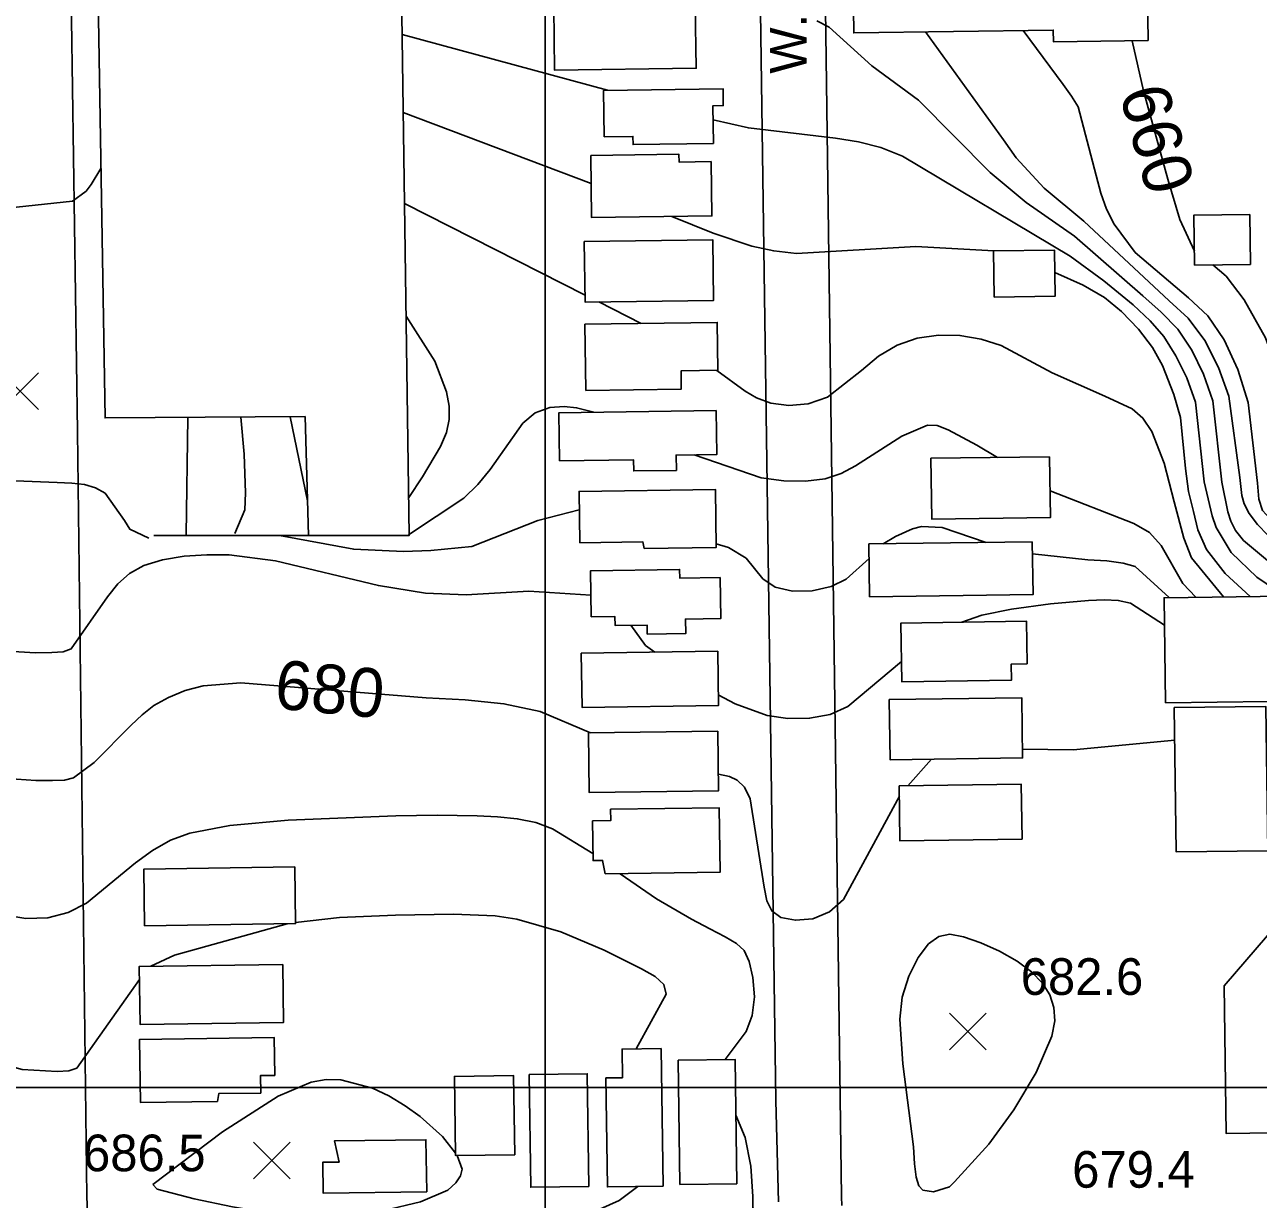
# Model space of a CAD drawing. Extents: x 79600 to 91800, y 75600 to 84400.
# Drawn here: x 80787 to 81292, y 77954 to 78435 of the extents above; entities that cross this region are included whole.
import ezdxf

# ---------------------------------------------------------------- set-up
doc = ezdxf.new("R2010")
doc.units = 0
for name, color, linetype in [('080-085$0$BLDG', 7, 'Continuous'), ('080-085$0$GRID', 7, 'Continuous'), ('080-085$0$INDEX', 7, 'Continuous'), ('080-085$0$INDXLBL', 7, 'Continuous'), ('080-085$0$INTER', 7, 'Continuous'), ('080-085$0$ROAD', 7, 'Continuous'), ('080-085$0$ROAD-NAME', 7, 'Continuous'), ('080-085$0$SPOTMARK', 7, 'Continuous'), ('080-085$0$SPOTS', 7, 'Continuous'), ('080-085$0$WALL', 7, 'Continuous')]:
    doc.layers.add(name, color=color, linetype=linetype)

# ---------------------------------------------------------------- blocks, each defined once
blk = doc.blocks.new('080-085$0$SPOTS')
at = {"layer": '080-085$0$SPOTMARK'}
for p, q in [((-0.5, -0.5), (0.5, 0.5)), ((-0.5, 0.5), (0.5, -0.5))]:
    blk.add_line(p, q, dxfattribs=at)

msp = doc.modelspace()

# ---------------------------------------------------------------- linework, layer by layer
at = {"layer": '080-085$0$BLDG'}
for points in [[(80925.81, 78506.36), (80926.78, 78456.84), (80816.71, 78454.12), (80819.72, 78274.15), (80901.62, 78274.69), (80903, 78226), (80944.3, 78226.06), (80940.99, 78458.77), (81076.3, 78462.25), (81074.62, 78582.1), (80949.62, 78579.81), (80950.92, 78507.27)], [(81125.3, 78509.93), (81126.36, 78431.78), (81208.04, 78432.89), (81208.1, 78428.14), (81246.86, 78428.67), (81246.24, 78474.46), (81223.47, 78474.15), (81222.97, 78511.25)], [(81003.49, 78442.16), (81061.46, 78442.98), (81061.82, 78417.26), (81003.85, 78416.45)], [(81024.15, 78389.23), (81035.94, 78389.4), (81035.99, 78386.06), (81068.88, 78386.52), (81068.66, 78401.93), (81072.91, 78401.99), (81072.81, 78408.93), (81023.89, 78408.25)], [(81018.64, 78381.59), (81054.77, 78382.09), (81054.82, 78378.88), (81067.93, 78379.07), (81068.24, 78356.85), (81019, 78356.16)], [(81288.5, 78357.46), (81288.78, 78337.02), (81265.95, 78336.71), (81265.67, 78357.15)], [(81016.01, 78346.36), (81068.6, 78347.09), (81068.95, 78322.27), (81016.35, 78321.54)], [(81183.63, 78342.52), (81208.53, 78342.85), (81208.79, 78323.95), (81183.89, 78323.61)], [(81016.66, 78285.43), (81055.73, 78285.97), (81055.63, 78293.42), (81070.7, 78293.63), (81070.43, 78313.23), (81016.28, 78312.47)], [(81005.85, 78256.55), (81036.19, 78256.98), (81036.26, 78252.44), (81053.7, 78252.69), (81053.61, 78258.94), (81070.22, 78259.17), (81069.96, 78277.14), (81005.57, 78276.24)], [(81206.56, 78258.28), (81206.9, 78233.37), (81158.27, 78232.72), (81157.93, 78257.62)], [(81014.15, 78223.07), (81039.94, 78223.44), (81040.53, 78220.7), (81070.05, 78221.11), (81069.72, 78244.86), (81013.86, 78244.08)], [(81199.46, 78223.46), (81199.76, 78201.83), (81132.84, 78200.93), (81132.55, 78222.55)], [(81018.86, 78192.67), (81028.56, 78192.81), (81028.61, 78189.19), (81041.7, 78189.37), (81041.75, 78185.66), (81057.53, 78185.88), (81057.44, 78191.79), (81071.88, 78191.99), (81071.64, 78208.81), (81055.09, 78208.58), (81055.04, 78212.12), (81018.59, 78211.61)], [(81197.4, 78173.47), (81190.84, 78173.38), (81190.93, 78166.75), (81145.98, 78166.14), (81145.66, 78190.19), (81197.16, 78190.89)], [(81014.75, 78177.86), (81070.62, 78178.64), (81070.93, 78156.41), (81015.06, 78155.63)], [(81140.89, 78158.89), (81141.23, 78134.19), (81195.5, 78134.93), (81195.17, 78159.62)], [(81257.61, 78155.57), (81258.41, 78096.48), (81295.89, 78096.99), (81295.09, 78156.07)], [(81017.66, 78145.17), (81070.68, 78145.91), (81071.02, 78121.51), (81018, 78120.77)], [(81195.28, 78101.64), (81194.97, 78124.17), (81144.97, 78123.49), (81145.27, 78100.96)], [(81024.59, 78087.48), (81023.46, 78092.99), (81019.6, 78092.93), (81019.37, 78109.18), (81026.85, 78109.28), (81026.79, 78113.94), (81071.21, 78114.56), (81071.58, 78088.14)], [(80897.42, 78090.31), (80897.75, 78067.15), (80835.94, 78066.28), (80835.62, 78089.44)], [(80892.52, 78050.42), (80892.85, 78026.71), (80834.05, 78025.88), (80833.71, 78049.6)], [(80889.24, 78005.02), (80883.38, 78004.93), (80883.48, 77997.76), (80866.3, 77997.52), (80865.73, 77994.38), (80834.24, 77993.94), (80833.88, 78019.74), (80889.03, 78020.51)], [(81048.23, 77959.64), (81047.44, 78015.99), (81031.45, 78015.77), (81031.61, 78004.05), (81024.84, 78003.95), (81025.47, 77959.32)], [(81078.48, 77960.66), (81077.77, 78011.52), (81054.46, 78011.19), (81055.18, 77960.34)], [(80987.5, 77972.48), (80987.05, 78004.92), (80962.82, 78004.58), (80963.27, 77972.14)], [(81017.86, 77959.54), (81017.21, 78005.65), (80993.42, 78005.32), (80994.07, 77959.21)], [(80915.57, 77969.53), (80908.91, 77969.44), (80909.09, 77956.78), (80951.45, 77957.37), (80951.15, 77978.67), (80913.69, 77978.15)]]:
    msp.add_lwpolyline(points, close=True, dxfattribs=at)
for points in [[(81332.1, 78201.63), (81253.45, 78200.56), (81254.03, 78157.53), (81317.54, 78158.39)], [(81308.56, 78077.02), (81278.01, 78041.73), (81278.83, 77981.26), (81317.44, 77981.78)]]:
    msp.add_lwpolyline(points, dxfattribs=at)
at = {"layer": '080-085$0$GRID'}
for p, q in [((81000, 80000), (81000, 76000)), ((85000, 78000), (80000, 78000))]:
    msp.add_line(p, q, dxfattribs=at)
at = {"layer": '080-085$0$INDEX'}
for p, q in [((80941.84, 78399.22), (81018.8, 78370.15)), ((80895.55, 78274.65), (80902.6, 78240.22)), ((81148.54, 78123.54), (81158.24, 78134.42))]:
    msp.add_line(p, q, dxfattribs=at)
for points in [[(81240.41, 78428.58), (81245.05, 78408.01), (81254.95, 78371.83), (81259.87, 78355.32), (81265.87, 78342.46)], [(81051.91, 78356.62), (81068.82, 78349.73), (81084.62, 78344.47), (81093.6, 78342.51), (81102.93, 78341.49), (81151.79, 78344.31), (81183.68, 78342.52)], [(81273.4, 78336.81), (81278.87, 78332.11), (81286.23, 78322.46), (81295.03, 78306.91), (81304.59, 78280.58)], [(81208.66, 78333.7), (81220.25, 78328.54), (81229.03, 78323.38), (81235.94, 78317.67), (81242.92, 78310.52), (81248.64, 78302.97), (81252.76, 78295.56), (81257.48, 78283.71), (81260.16, 78274.29), (81262.21, 78253.46), (81263.49, 78244.09), (81265.47, 78235.8), (81267.3, 78228.36), (81270.76, 78220.31), (81278.49, 78210.51), (81288.71, 78201.04)], [(80748.73, 78142.83), (80764.53, 78133.64), (80769.62, 78130.38), (80775.9, 78127.75), (80783.52, 78126.29), (80791.43, 78125.76), (80798.26, 78125.7), (80803.08, 78125.88), (80806.74, 78126.76), (80815.28, 78133.06), (80830.48, 78148.42), (80834.86, 78152.65), (80839.76, 78156.4), (80845.73, 78159.74), (80852.59, 78162.51), (80859.94, 78164.47), (80875.27, 78165.74), (80951.21, 78159.56), (80967.23, 78158.68), (80983.05, 78157.11), (80997.9, 78153.94), (81018.47, 78145.18)], [(81195.45, 78138.5), (81216.18, 78138.29), (81257.8, 78142.18)], [(81070.93, 78128.31), (81075.49, 78127.34), (81078.64, 78125.9), (81081.66, 78123), (81083.97, 78118.24), (81089.7, 78081.99), (81090.8, 78076.44), (81092.8, 78072.35), (81096.53, 78069.7), (81102.44, 78068.52), (81109.55, 78069.12), (81116.47, 78071.89), (81122.17, 78077.01), (81145.03, 78119.33)]]:
    msp.add_lwpolyline(points, dxfattribs=at)
at = {"layer": '080-085$0$INTER'}
for p, q in [((80941.38, 78431.17), (81025.45, 78408.27)), ((80942.37, 78361.93), (81016.31, 78324.39)), ((81021.9, 78321.61), (81039.26, 78312.79)), ((80853.57, 78274.37), (80853, 78226.27)), ((81023.35, 78092.99), (81023.48, 78092.89))]:
    msp.add_line(p, q, dxfattribs=at)
for points in [[(81111.26, 78436.64), (81116.23, 78434.17), (81133.79, 78418.24), (81152.86, 78404.16), (81182.28, 78374.58), (81196.94, 78362.27), (81216.79, 78348.61), (81244.7, 78324.14), (81252.28, 78317.47), (81259.05, 78310.43), (81264.76, 78301.92), (81269.64, 78292.06), (81273.4, 78281.13), (81277.14, 78247.86), (81279.51, 78235.65), (81280.77, 78231.91), (81282.75, 78228.05), (81285.99, 78223.91), (81296.62, 78215.03)], [(81195.77, 78432.72), (81212.1, 78410.6), (81215.57, 78405.87), (81218.25, 78401.46), (81225.57, 78373.32), (81227.48, 78366.11), (81229.85, 78359.58), (81232.98, 78353.44), (81241.64, 78341.88), (81263.4, 78323.3), (81271.34, 78315.95), (81278.1, 78306.13), (81283.71, 78293.97), (81287.92, 78280.47), (81291.7, 78247.48), (81292.24, 78240.95), (81293.71, 78236.21), (81296.71, 78232.96), (81302.26, 78231.06), (81343.88, 78234.3)], [(81155.76, 78432.18), (81187.64, 78387.94), (81192.9, 78380.67), (81204.4, 78368.14), (81220.58, 78354.7), (81255.58, 78322.14), (81263.35, 78314.93), (81270.17, 78305.79), (81275.75, 78294.72), (81279.91, 78283), (81284.45, 78249.73), (81285.23, 78242.45), (81286.23, 78238.91), (81288.27, 78234.99), (81291.66, 78230.55), (81295.98, 78226.12), (81300.61, 78222.39), (81305.11, 78219.97), (81309.7, 78218.94), (81333.63, 78225.34), (81354.22, 78228.72)], [(81068.74, 78396.2), (81083.18, 78392.86), (81118.9, 78388.61), (81128.28, 78387.17), (81137.43, 78384.85), (81146.31, 78381.31), (81215.01, 78340.3), (81228.73, 78330.24), (81240.77, 78320.45), (81247.75, 78313.92), (81253.3, 78307.42), (81258.29, 78299.55), (81262.81, 78290.59), (81266.32, 78280.66), (81269.87, 78248.05), (81273.11, 78234.06), (81274.8, 78229.27), (81280.85, 78219.1), (81291.43, 78208.99), (81302.86, 78201.23)], [(80818.01, 78376.3), (80814.04, 78369.74), (80812.01, 78366.99), (80806.46, 78362.85), (80779.7, 78359.98), (80774.94, 78359.66), (80771.59, 78358.57), (80764.48, 78351.2), (80748.68, 78328.46)], [(80944.08, 78241.58), (80949.77, 78250.01), (80957.14, 78262.44), (80959.51, 78268.17), (80960.65, 78273.52), (80960.65, 78278.96), (80959.62, 78284.85), (80954.85, 78297.39), (80943.02, 78315.83)], [(81070.29, 78293.62), (81081.93, 78285.07), (81086.54, 78282.37), (81092.43, 78280.25), (81099.72, 78279.28), (81107.74, 78279.92), (81115.65, 78282.63), (81129.58, 78293.61), (81136.54, 78299.44), (81144.15, 78303.89), (81152.36, 78306.76), (81161, 78308.09), (81169.86, 78307.92), (81178.57, 78306.44), (81186.69, 78303.86), (81207.63, 78292.57), (81229.13, 78283.02), (81240.42, 78277.9), (81244.79, 78274.08), (81248.37, 78268.65), (81253.43, 78255.66), (81257.51, 78239.85), (81261.57, 78224.89), (81264.73, 78216.83), (81277.72, 78200.89)], [(81019.92, 78276.44), (81012.81, 78278.29), (81007.8, 78278.76), (81001.87, 78278.37), (80995.94, 78276.28), (80990.76, 78271.94), (80977.39, 78253), (80972.46, 78246.94), (80966.68, 78241.28), (80943.96, 78226.32)], [(80875.33, 78274.52), (80876.73, 78259.26), (80877.27, 78243.53), (80876.94, 78236.58), (80872.94, 78226.82)], [(81185.24, 78257.99), (81176.72, 78263.04), (81165.08, 78269.33), (81160.53, 78271.02), (81156.49, 78271.2), (81146.09, 78266.7), (81127.07, 78254.47), (81121.23, 78251.35), (81114.61, 78249.2), (81106.63, 78248.2), (81097.7, 78248.36), (81088.49, 78249.65), (81061.02, 78259.04)], [(80760.81, 78251.06), (80765.91, 78249.12), (80800.11, 78247.71), (80806.07, 78247.5), (80811.25, 78246.84), (80815.83, 78245.5), (80819.77, 78243.33), (80827.69, 78232.11), (80829.82, 78228.66), (80837.69, 78224.94)], [(81266.4, 78200.74), (81261.14, 78206.37), (81252.25, 78221.96), (81247.48, 78227.23), (81241.04, 78230.96), (81206.75, 78244.35)], [(80891.16, 78226.01), (80921.59, 78220.38), (80941.98, 78219.43), (80953.16, 78219.83), (80969.87, 78221.48), (80997.02, 78232.18), (81013.96, 78236.54)], [(81138.44, 78222.63), (81143.41, 78225.57), (81150.44, 78228.72), (81154.09, 78229.65), (81162.5, 78229.23), (81180.61, 78223.2)], [(81070.03, 78222.57), (81075.09, 78221.1), (81082.3, 78216.69), (81089.11, 78208.32), (81094.13, 78204.86), (81101.22, 78203.23), (81109.35, 78203.43), (81117.07, 78205.2), (81123.21, 78208.17), (81132.63, 78216.56)], [(80777.58, 78178.75), (80791.22, 78178.01), (80797.94, 78178.11), (80802.61, 78178.41), (80805.88, 78179.6), (80820.68, 78200.84), (80824.92, 78206.27), (80829.68, 78210.52), (80835.66, 78213.72), (80843.29, 78216.03), (80852.1, 78217.49), (80861.37, 78218.16), (80870.58, 78218.06), (80889.53, 78215.59), (80931.66, 78205.49), (80950.94, 78202.37), (80967.65, 78201.67), (80993.25, 78203.28), (81018.73, 78201.63)], [(81199.53, 78218.57), (81222.16, 78216.07), (81229.95, 78215.58), (81236.74, 78214.73), (81241.54, 78213.28), (81255.49, 78200.59)], [(81170.57, 78190.53), (81178.74, 78193.36), (81190.97, 78195.91), (81206.91, 78198.1), (81222.54, 78199.39), (81229.03, 78199.69), (81234.66, 78199.45), (81239.72, 78198.3), (81253.6, 78189.31)], [(81035.09, 78189.28), (81041.07, 78181.04), (81044.88, 78178.28)], [(81070.87, 78160.81), (81077.85, 78157.06), (81090.89, 78152.38), (81099.38, 78151.14), (81108.29, 78151.19), (81116.72, 78152.78), (81123.93, 78156), (81145.87, 78174.39)], [(80742.01, 78088.8), (80761.58, 78077.65), (80769.49, 78073.79), (80778.19, 78070.74), (80787.26, 78069.24), (80796.23, 78069.51), (80804.65, 78071.63), (80812.18, 78075.54), (80832.26, 78092.02), (80839.16, 78097.1), (80846.5, 78101.23), (80854.4, 78104.12), (80870.82, 78107.26), (80894.78, 78109.45), (80938.8, 78111.25), (80955.8, 78111.47), (80972.11, 78111.29), (80980.42, 78110.91), (80988.57, 78110.07), (80996.19, 78108.47), (81002.93, 78105.98), (81019.56, 78095.8)], [(81030.66, 78087.56), (81045.6, 78077.33), (81059.95, 78068.94), (81067.35, 78065.02), (81073.68, 78061.69), (81078.29, 78059.03), (81081.42, 78056.09), (81083.57, 78051.69), (81085.08, 78045.09), (81085.64, 78037.22), (81084.76, 78029.46), (81082.24, 78022.94), (81073.64, 78011.46)], [(80897.74, 78067.59), (80915.77, 78069.67), (80938.72, 78070.58), (80962.47, 78070.94), (80979.45, 78070.25), (80988.3, 78068.97), (81006.37, 78063.76), (81024.18, 78056.28), (81039.48, 78048.66), (81045.05, 78045.42), (81048.56, 78042.17), (81049.46, 78038.3), (81037.27, 78015.85)], [(80838.43, 78049.66), (80848.18, 78054.16), (80894.28, 78067.1)], [(80743.55, 78052.63), (80750.44, 78050.33), (80755.15, 78047.92), (80759.95, 78043.83), (80764.11, 78037.81), (80770.18, 78023.59), (80772.33, 78017.45), (80774.94, 78012.61), (80779.19, 78009.25), (80785.77, 78007.42), (80800.18, 78006.62), (80804.88, 78006.84), (80808.14, 78008), (80833.79, 78044.2)], [(80963.26, 77973.1), (80957.87, 77979.98), (80948.8, 77988.14), (80942.61, 77992.56), (80935.93, 77996.57), (80929.2, 77999.76), (80916.26, 78003.2), (80910.23, 78003.31), (80904.19, 78002.26), (80890.67, 77996.48), (80867.81, 77981.91), (80839.36, 77960.37)], [(81078.09, 77988.72), (81081.83, 77979.64), (81084.26, 77967.84), (81084.99, 77955.36), (81084.99, 77950.97), (81085.91, 77947.86), (81089.03, 77945.62), (81102.61, 77942.56), (81109.53, 77941.57), (81114.3, 77940.72), (81117.17, 77939.1), (81121.87, 77922.25), (81124.91, 77914.35), (81129.86, 77907.06), (81142.63, 77893.61), (81154.91, 77881.16), (81161.4, 77877.3), (81168.69, 77876.1), (81193.56, 77879.96), (81211.45, 77882.32), (81337.3, 77887.22)], [(80839.36, 77960.37), (80841.05, 77958.42), (80856.18, 77954.52), (80871.97, 77951.21), (80888.87, 77948.37), (80907.55, 77947.39), (80916.86, 77947.68), (80933.98, 77949.73), (80948.94, 77953.26), (80960.15, 77958.07), (80963.45, 77960.97), (80965.29, 77963.91), (80965.97, 77966.59), (80963.94, 77972.15)], [(81037.96, 77959.5), (81030.25, 77953.74), (81018.38, 77948.42), (81002.45, 77943.54), (80994.53, 77941.15), (80987.66, 77938.06), (80982.66, 77933.48), (80980.19, 77926.98), (80980.42, 77919.84), (80983.35, 77913.69), (80988.84, 77909.79), (80996.19, 77907.71), (81021.91, 77905.16), (81067.19, 77903.97), (81084.81, 77903.41), (81092.43, 77902.67), (81099.3, 77901.3), (81105.65, 77898.96), (81123.3, 77886.35)]]:
    msp.add_lwpolyline(points, dxfattribs=at)
msp.add_lwpolyline([(81167.61, 77961.45), (81181.62, 77976.83), (81191.9, 77990.84), (81201.1, 78006.21), (81207.47, 78021.02), (81208.64, 78027.29), (81208.35, 78032.85), (81206.65, 78037.93), (81203.6, 78042.76), (81199.16, 78047.37), (81193.26, 78051.75), (81186.02, 78055.83), (81178.35, 78059.29), (81171.32, 78061.73), (81165.72, 78062.75), (81161.17, 78061.92), (81156.99, 78058.82), (81152.74, 78053.21), (81148.9, 78045.68), (81146.2, 78037.06), (81145.17, 78028.03), (81146.51, 78009.76), (81150.77, 77975.79), (81151.22, 77968.77), (81151.86, 77963.31), (81152.97, 77959.84), (81154.58, 77958.04), (81159.05, 77957.4), (81165.54, 77959.38)], close=True, dxfattribs=at)
at = {"layer": '080-085$0$ROAD'}
for points in [[(81121.52, 77951.67), (81121.36, 77955.3), (81112.84, 78583.39), (81113.08, 78587.99), (81113.63, 78589.81), (81115.56, 78592.34), (81117.5, 78594.03), (81119.17, 78594.88), (81122.23, 78595.74), (81125.44, 78595.91), (81589.43, 78605.3)], [(81086.25, 78576.33), (81094.38, 77994.56), (81095.56, 77953.27)], [(80812.49, 77948.85), (80812.3, 77955.27), (80808.47, 78268.62), (80805.22, 78493.65)]]:
    msp.add_lwpolyline(points, dxfattribs=at)
at = {"layer": '080-085$0$WALL'}
msp.add_line((80839.67, 78226.01), (80902.97, 78226.01), dxfattribs=at)

# ---------------------------------------------------------------- block references
at = {"layer": '080-085$0$SPOTMARK', "xscale": 15, "yscale": 15}
for p in [(80784.97, 78285.16), (81173.04, 78022.96), (80888.08, 77970.15)]:
    msp.add_blockref('080-085$0$SPOTS', p, dxfattribs=at)

# ---------------------------------------------------------------- texts
at = {"layer": '080-085$0$INDXLBL'}
for s, rotation, p in [('660', 285.5277, (81234.99, 78407.29)), ('680', 354.6318, (80888.65, 78155.31))]:
    msp.add_text(s, height=20, rotation=rotation, dxfattribs=at).set_placement(p)
at = {"layer": '080-085$0$ROAD-NAME'}
msp.add_text('W. 40 ST.', height=15, rotation=90.1619, dxfattribs=at).set_placement((81107.1, 78415.11))
at = {"layer": '080-085$0$SPOTS'}
for s, p in [('682.6', (81194.73, 78037.96)), ('686.5', (80810.7, 77965.76)), ('679.4', (81215.81, 77959.02))]:
    msp.add_text(s, height=15, dxfattribs=at).set_placement(p)

doc.saveas('drawing.dxf')
